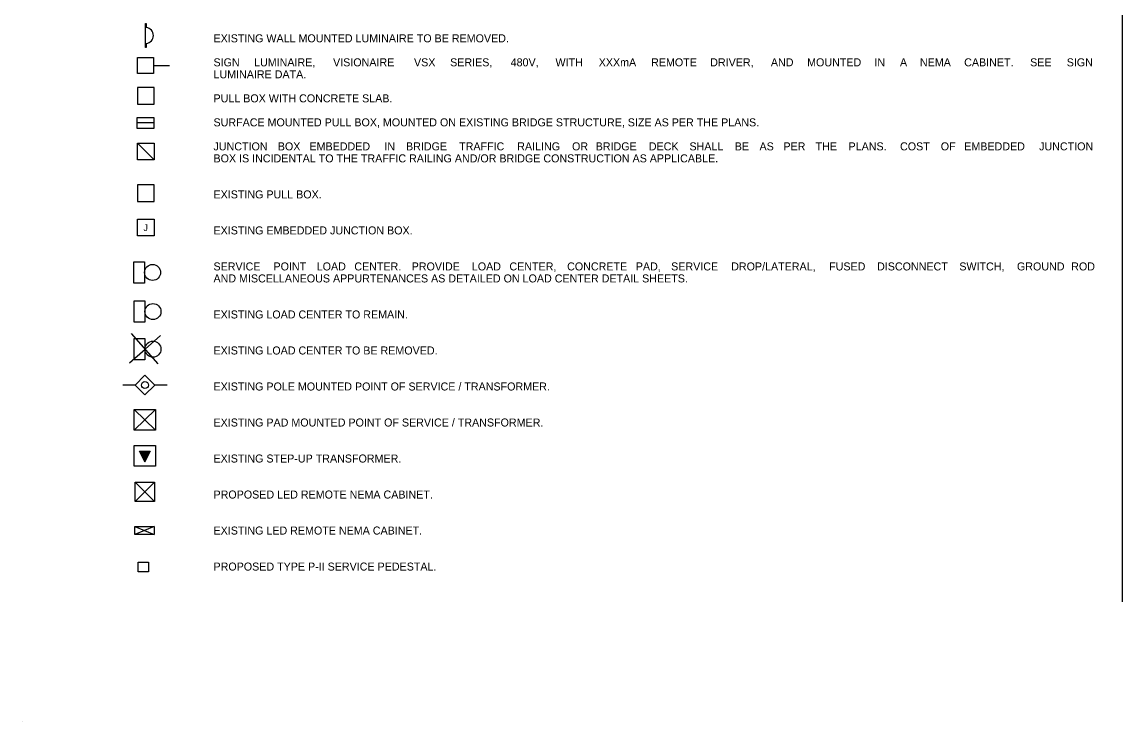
# Model space of a CAD drawing. Extents: x -1452 to -654, y -278 to 245.
# Drawn here: x -1451.7 to -1039.2, y -278.3 to -16 of the extents above; entities that cross this region are included whole.
import ezdxf

# ---------------------------------------------------------------- set-up
doc = ezdxf.new("R2010")
doc.units = 0
for name, color, linetype in [('AdhocPoint_dp', 7, 'Continuous'), ('ControllerP', 7, 'Continuous'), ('Default', 7, 'Continuous'), ('ElecMisc_ep', 7, 'Continuous'), ('JunctBoxA', 7, 'Continuous'), ('LoadCenter', 7, 'Continuous'), ('Miscellaneous3', 7, 'Continuous'), ('SheetBorder_dp', 7, 'Continuous'), ('SheetLines_dp', 7, 'Continuous'), ('SignPanel', 7, 'Continuous')]:
    doc.layers.add(name, color=color, linetype=linetype)

msp = doc.modelspace()

# ---------------------------------------------------------------- linework, layer by layer
at = {"layer": 'AdhocPoint_dp'}
for p, q in [((-1405.39, -25.52), (-1405.39, -16.52)), ((-1405.39, -16.52), (-1405.09, -16.52)), ((-1405.09, -16.52), (-1405.09, -18.04)), ((-1405.09, -24.01), (-1405.09, -25.52)), ((-1405.09, -25.52), (-1405.39, -25.52))]:
    msp.add_line(p, q, dxfattribs=at)
msp.add_arc((-1405.39, -21.02), 3, 275.7392, 84.2608, dxfattribs=at)
at = {"layer": 'ControllerP'}
for p, q in [((-1409.27, -188.4), (-1401.98, -195.64)), ((-1409.27, -195.64), (-1401.98, -188.4)), ((-1409.3, -205.02), (-1402.08, -208.03)), ((-1402.08, -205.02), (-1409.3, -208.03)), ((-1409.3, -205.02), (-1402.08, -205.02)), ((-1409.3, -208.03), (-1409.3, -205.02)), ((-1402.08, -205.02), (-1402.08, -208.03)), ((-1402.08, -208.03), (-1409.3, -208.03))]:
    msp.add_line(p, q, dxfattribs=at)
for points in [[(-1409.27, -188.4), (-1401.98, -188.4), (-1401.98, -195.64), (-1409.27, -195.64)], [(-1408.08, -218.44), (-1404.18, -218.44), (-1404.18, -222.02), (-1408.08, -222.02)]]:
    msp.add_lwpolyline(points, close=True, dxfattribs=at)
at = {"layer": 'Default'}
msp.add_circle((-1405.56, -152.03), 1.3, dxfattribs=at)
at = {"layer": 'ElecMisc_ep'}
for p, q in [((-1409.57, -168.9), (-1401.56, -161.14)), ((-1409.57, -161.14), (-1401.56, -168.91)), ((-1405.56, -180.82), (-1407.56, -176.82)), ((-1407.56, -176.82), (-1403.56, -176.82)), ((-1407.36, -176.82), (-1405.56, -180.82)), ((-1405.56, -180.82), (-1407.16, -176.82)), ((-1405.56, -180.82), (-1406.96, -176.82)), ((-1405.56, -180.82), (-1406.76, -176.82)), ((-1405.56, -180.82), (-1406.56, -176.82)), ((-1405.56, -180.82), (-1406.36, -176.82)), ((-1405.56, -180.82), (-1406.16, -176.82)), ((-1405.56, -180.82), (-1405.96, -176.82)), ((-1405.56, -180.82), (-1405.76, -176.82)), ((-1405.56, -180.82), (-1405.36, -176.82)), ((-1405.56, -180.82), (-1405.16, -176.82)), ((-1405.56, -180.82), (-1404.96, -176.82)), ((-1405.56, -180.82), (-1404.76, -176.82)), ((-1405.56, -180.82), (-1404.36, -176.82)), ((-1405.56, -180.82), (-1404.16, -176.82)), ((-1405.56, -180.82), (-1403.96, -176.82)), ((-1405.56, -180.82), (-1403.77, -176.82)), ((-1403.56, -176.82), (-1405.56, -180.82)), ((-1405.56, -180.82), (-1405.56, -176.82)), ((-1405.56, -180.82), (-1404.56, -176.82))]:
    msp.add_line(p, q, dxfattribs=at)
for points in [[(-1409.57, -161.14), (-1401.56, -161.14), (-1401.56, -168.91), (-1409.57, -168.9)], [(-1409.57, -174.64), (-1401.56, -174.64), (-1401.56, -182.41), (-1409.57, -182.4)]]:
    msp.add_lwpolyline(points, close=True, dxfattribs=at)
at = {"layer": 'JunctBoxA'}
for p, q in [((-1408.51, -55.88), (-1408.51, -51.71)), ((-1408.51, -51.71), (-1402.26, -51.71)), ((-1402.26, -51.71), (-1402.26, -55.88)), ((-1402.26, -53.8), (-1408.51, -53.8)), ((-1402.26, -55.88), (-1408.51, -55.88))]:
    msp.add_line(p, q, dxfattribs=at)
msp.add_lwpolyline([(-1402.26, -53.8), (-1408.51, -53.8), (-1408.51, -51.71), (-1402.26, -51.71)], close=True, dxfattribs=at)
at = {"layer": 'LoadCenter'}
for p, q in [((-1402.39, -32.21), (-1396.39, -32.21)), ((-1409.7, -105.83), (-1405.7, -105.83)), ((-1409.7, -113.83), (-1409.7, -105.83)), ((-1405.7, -105.83), (-1405.7, -113.83)), ((-1405.7, -113.83), (-1409.7, -113.83)), ((-1409.56, -120.49), (-1405.56, -120.49)), ((-1409.56, -128.49), (-1409.56, -120.49)), ((-1405.56, -120.49), (-1405.56, -128.49)), ((-1405.56, -128.49), (-1409.56, -128.49)), ((-1410.7, -132.71), (-1400.68, -144.11)), ((-1409.56, -134.58), (-1405.56, -134.58)), ((-1409.56, -142.58), (-1409.56, -134.58)), ((-1405.56, -134.58), (-1405.56, -142.58)), ((-1405.51, -138.62), (-1399.69, -133.5)), ((-1411.32, -143.73), (-1405.51, -138.62)), ((-1405.56, -142.58), (-1409.56, -142.58)), ((-1409.24, -152.03), (-1405.56, -148.35)), ((-1405.56, -148.35), (-1401.89, -152.03)), ((-1409.24, -152.03), (-1413.88, -152.03)), ((-1405.56, -155.7), (-1409.24, -152.03)), ((-1401.89, -152.03), (-1405.56, -155.7)), ((-1397.24, -152.03), (-1401.89, -152.03))]:
    msp.add_line(p, q, dxfattribs=at)
for points in [[(-1408.39, -29.21), (-1402.39, -29.21), (-1402.39, -35.21), (-1408.39, -35.21)], [(-1409.7, -105.83), (-1405.7, -105.83), (-1405.7, -113.83), (-1409.7, -113.83)]]:
    msp.add_lwpolyline(points, close=True, dxfattribs=at)
for centre in [(-1402.7, -109.83), (-1402.7, -109.83), (-1402.56, -124.49), (-1402.56, -138.58)]:
    msp.add_circle(centre, 3, dxfattribs=at)
at = {"layer": 'Miscellaneous3'}
msp.add_line((-1039.17, 240.54), (-1039.17, -233.32), dxfattribs=at)
at = {"layer": 'SheetLines_dp'}
for p, q in [((-1408.35, -61.38), (-1402.1, -61.38)), ((-1408.35, -67.63), (-1408.35, -61.38)), ((-1408.35, -61.38), (-1402.1, -67.63)), ((-1402.1, -61.38), (-1402.1, -67.63)), ((-1402.1, -67.63), (-1408.35, -67.63)), ((-1408.42, -89.9), (-1402.17, -89.9)), ((-1408.42, -96.15), (-1408.42, -89.9)), ((-1402.17, -89.9), (-1402.17, -96.15)), ((-1402.17, -96.15), (-1408.42, -96.15))]:
    msp.add_line(p, q, dxfattribs=at)
for points in [[(-1408.39, -46.7), (-1402.14, -46.7), (-1402.14, -40.45), (-1408.39, -40.45)], [(-1408.35, -83.25), (-1402.1, -83.25), (-1402.1, -77), (-1408.35, -77)]]:
    msp.add_lwpolyline(points, close=True, dxfattribs=at)
at = {"layer": 'SignPanel'}
msp.add_line((-1451.67, -278.32), (-1451.67, -278.32), dxfattribs=at)

# ---------------------------------------------------------------- texts
at = {"layer": 'SheetBorder_dp'}
for s, p in [('EXISTING WALL MOUNTED LUMINAIRE TO BE REMOVED.', (-1379.86, -23.57)), ('SIGN ', (-1379.86, -32.57)), ('LUMINAIRE, ', (-1364.64, -32.57)), ('VISIONAIRE ', (-1335.02, -32.57)), ('VSX ', (-1304.67, -32.57)), ('SERIES, ', (-1291.12, -32.57)), ('480V, ', (-1268.42, -32.57)), ('WITH ', (-1251.61, -32.57)), ('XXXmA ', (-1235.4, -32.57)), ('REMOTE ', (-1215.76, -32.57)), ('DRIVER, ', (-1193.59, -32.57)), ('AND ', (-1170.84, -32.57)), ('MOUNTED ', (-1157.25, -32.57)), ('IN ', (-1132.03, -32.57)), ('A ', (-1122.43, -32.57)), ('NEMA ', (-1114.94, -32.57)), ('CABINET. ', (-1098.36, -32.57)), ('SEE ', (-1073.62, -32.57)), ('SIGN ', (-1059.9, -32.57)), ('LUMINAIRE DATA.', (-1379.86, -37.07)), ('PULL BOX WITH CONCRETE SLAB. ', (-1379.86, -46.07)), ('SURFACE MOUNTED PULL BOX, MOUNTED ON EXISTING BRIDGE STRUCTURE, SIZE AS PER THE PLANS.', (-1379.86, -55.07)), ('JUNCTION ', (-1379.86, -64.07)), ('BOX ', (-1355.75, -64.07)), ('EMBEDDED ', (-1343.87, -64.07)), ('IN ', (-1315.79, -64.07)), ('BRIDGE ', (-1307.66, -64.07)), ('TRAFFIC ', (-1287.74, -64.07)), ('RAILING ', (-1265.96, -64.07)), ('OR ', (-1245.41, -64.07)), ('BRIDGE ', (-1236.53, -64.07)), ('DECK ', (-1216.62, -64.07)), ('SHALL ', (-1201.37, -64.07)), ('BE ', (-1184.39, -64.07)), ('AS ', (-1175.11, -64.07)), ('PER ', (-1166.14, -64.07)), ('THE ', (-1154.08, -64.07)), ('PLANS. ', (-1141.72, -64.07)), (' COST ', (-1123.52, -64.07)), ('OF ', (-1107.13, -64.07)), ('EMBEDDED ', (-1098.32, -64.07)), ('JUNCTION ', (-1070.25, -64.07)), ('BOX IS INCIDENTAL TO THE TRAFFIC RAILING AND/OR BRIDGE CONSTRUCTION AS APPLICABLE. ', (-1379.86, -68.57)), ('EXISTING PULL BOX.', (-1379.86, -82.07)), ('EXISTING EMBEDDED JUNCTION BOX.', (-1379.86, -95.57)), ('SERVICE ', (-1379.86, -109.07)), ('POINT ', (-1357.36, -109.07)), ('LOAD ', (-1341.15, -109.07)), ('CENTER. ', (-1327.05, -109.07)), ('PROVIDE ', (-1305.54, -109.07)), ('LOAD ', (-1282.98, -109.07)), ('CENTER, ', (-1268.88, -109.07)), ('CONCRETE ', (-1247.25, -109.07)), ('PAD, ', (-1221.5, -109.07)), ('SERVICE ', (-1208.23, -109.07)), ('DROP/LATERAL, ', (-1185.73, -109.07)), ('FUSED ', (-1149, -109.07)), ('DISCONNECT ', (-1131.02, -109.07)), ('SWITCH, ', (-1100.18, -109.07)), ('GROUND ', (-1078.56, -109.07)), ('ROD ', (-1058.22, -109.07)), ('AND MISCELLANEOUS APPURTENANCES AS DETAILED ON LOAD CENTER DETAIL SHEETS.  ', (-1379.86, -113.57)), ('EXISTING LOAD CENTER TO REMAIN.', (-1379.86, -127.07)), ('EXISTING LOAD CENTER TO BE REMOVED.', (-1379.86, -140.57)), ('EXISTING POLE MOUNTED POINT OF SERVICE / TRANSFORMER.', (-1379.86, -154.07)), ('EXISTING PAD MOUNTED POINT OF SERVICE / TRANSFORMER.', (-1379.86, -167.57)), ('EXISTING STEP-UP TRANSFORMER.', (-1379.86, -181.07)), ('PROPOSED LED REMOTE NEMA CABINET.', (-1379.86, -194.57)), ('EXISTING LED REMOTE NEMA CABINET.', (-1379.86, -208.07)), ('PROPOSED TYPE P-II SERVICE PEDESTAL.', (-1379.86, -221.57))]:
    msp.add_text(s, height=3, dxfattribs=at).set_placement(p)
at = {"layer": 'SheetLines_dp'}
msp.add_text('J', height=2.5, dxfattribs=at).set_placement((-1406.14, -94.27))

doc.saveas('drawing.dxf')
